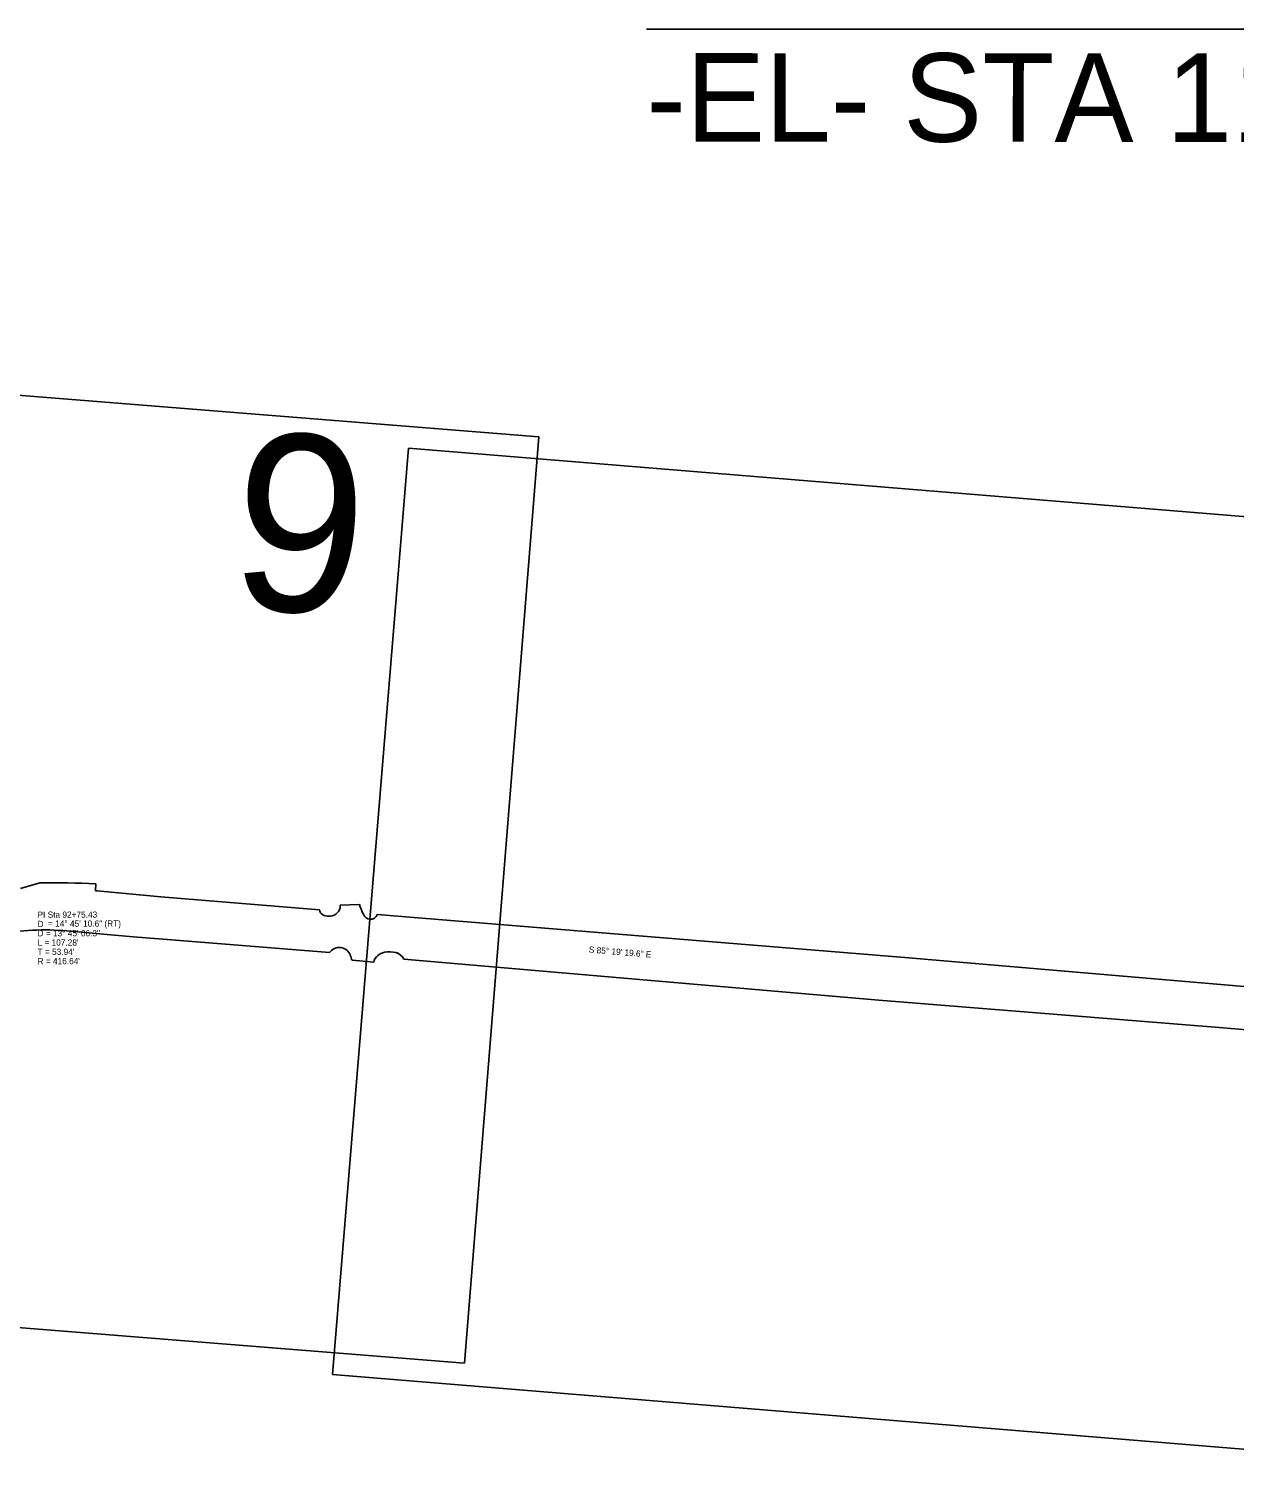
# Model space of a CAD drawing. Extents: x 925297 to 940193, y 663541 to 689899.
# Drawn here: x 935468 to 936830, y 683818 to 685461 of the extents above; entities that cross this region are included whole.
import ezdxf

# ---------------------------------------------------------------- set-up
doc = ezdxf.new("R2010")
doc.units = 0
for name, color, linetype in [('Default', 7, 'Continuous'), ('Exist Horizontal Alignment Curve and Spiral Data', 7, 'Continuous'), ('Exist Horizontal Alignment Direction Label', 7, 'Continuous'), ('Exist Horizontal Alignment Tick Large', 7, 'Continuous'), ('Prop DSN Text', 7, 'Continuous'), ('Prop Shade Light', 7, 'Continuous')]:
    doc.layers.add(name, color=color, linetype=linetype)

msp = doc.modelspace()

# ---------------------------------------------------------------- linework, layer by layer
at = {"layer": 'Default'}
for p, q in [((936044, 685000.2), (934548.7, 685119.8)), ((935896.8, 684987.3), (935811.2, 683940.8)), ((937391.9, 684865), (935896.8, 684987.3)), ((935960.3, 683953.6), (936044, 685000.2)), ((934465, 684073.2), (935960.3, 683953.6)), ((935811.2, 683940.8), (937306.2, 683818.5))]:
    msp.add_line(p, q, dxfattribs=at)
at = {"layer": 'Exist Horizontal Alignment Tick Large'}
msp.add_line((936165.7, 685461), (938206.6, 685461), dxfattribs=at)
at = {"layer": 'Prop Shade Light'}
for p, q in [((935458.8, 684490), (935480.5, 684496.3)), ((935543.9, 684495.2), (935543.6, 684487.5)), ((935545.5, 684487.4), (935617.1, 684480.7)), ((935617.1, 684480.7), (935796.3, 684466)), ((935819.8, 684471.1), (935841.5, 684472.1)), ((935861.4, 684460.7), (936457.4, 684411.9)), ((935586.1, 684435.4), (935506.7, 684442.4)), ((935619.7, 684432.7), (935586.1, 684435.4)), ((935807.8, 684417.6), (935619.7, 684432.7)), ((936427.9, 684364), (935891.7, 684410.2)), ((936457.4, 684411.9), (937265.8, 684343.4)), ((935857.6, 684406.9), (935833.2, 684408.9)), ((936812.4, 684333.1), (936427.9, 684364)), ((936847.8, 684329.9), (936812.4, 684333.1))]:
    msp.add_line(p, q, dxfattribs=at)
for centre, radius, start, end in [((935493.3, 683464.8), 1031.7, 87.1902, 90.7129), ((935472.3, 683501.5), 988.6, 85.7534, 85.8658), ((935803.9, 684466.7), 7.58, 185.2719, 240.1528), ((935807.3, 684478), 19.3, 247.973, 268.4102), ((935807.6, 684471.1), 12.4, 266.3206, 345.5574), ((935766.2, 684473.3), 53.7, 354.2996, 357.6562), ((935914.3, 684494.6), 76.2, 197.2095, 206.0916), ((935854, 684463.9), 8.55, 198.8814, 267.2485), ((935854.6, 684462.2), 6.93, 261.4162, 347.4457), ((935486, 684164.2), 279, 85.7469, 101.8761), ((935818.8, 684410.3), 13.1, 18.797, 146.4548), ((935764.8, 684388), 71.5, 17.0088, 21.8062), ((935872.3, 684403), 15.2, 99.0087, 165.3386), ((935875.2, 684388.6), 29.9, 75.4974, 100.1543), ((935878.3, 684402.9), 15.3, 28.4866, 73.1192)]:
    msp.add_arc(centre, radius, start, end, dxfattribs=at)

# ---------------------------------------------------------------- texts
at = {"layer": 'Exist Horizontal Alignment Curve and Spiral Data'}
for s, p in [('PI Sta 92+75.43', (935478, 684457)), ('D', (935478, 684446.5)), ('D = 13%%d 45\' 06.3"', (935478, 684436)), ('= 14%%d 45\' 10.6" (RT)', (935489.8, 684446.9)), ("L = 107.28'", (935478, 684425.5)), ("T = 53.94'", (935478, 684415)), ("R = 416.64'", (935478, 684404.5))]:
    msp.add_text(s, height=7, dxfattribs=at).set_placement(p)
at = {"layer": 'Exist Horizontal Alignment Direction Label'}
msp.add_text('S 85%%d 19\' 19.6" E', height=7, rotation=355.3221, dxfattribs=at).set_placement((936100.3, 684417.7))
at = {"layer": 'Exist Horizontal Alignment Tick Large'}
msp.add_text('-EL- STA 110+99.43', height=100, rotation=359.9706, dxfattribs=at).set_placement((936165.7, 685333.8))
at = {"layer": 'Prop DSN Text'}
msp.add_text('9', height=200, rotation=355.4277, dxfattribs=at).set_placement((935692.2, 684808.8))

doc.saveas('drawing.dxf')
